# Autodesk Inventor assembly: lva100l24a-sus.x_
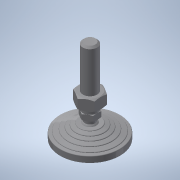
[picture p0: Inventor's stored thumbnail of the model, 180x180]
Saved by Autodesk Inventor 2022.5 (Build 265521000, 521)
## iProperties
Part Number: lva100l24a-sus.x_
Material: 一般
Document SubType Name: Assembly
Designer: ImaoCorp
Sending System: SOLIDWORKS 2017-2017317
MC: AMD64
MC_MODEL: Intel64 Family 6 Model 60 Stepping 3, GenuineIntel
OS: Windows_NT
FRU: Parasolid Version 29.0, build 201,  4-17-2017
FORMAT: text
GUISE: transmit
KEY: lva100l24a-sus
FILE: lva100l24a-sus.x_t
DATE: Mon Jul 01 18:04:37 2019
Author: ImaoCorp
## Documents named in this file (3)
- X:\14_SW2022-Inv2022\00_全2023-1023新製品(TCC)まで\l\lva100l24a-sus\LVA100L24A-SUS.iam
- X:\14_SW2022-Inv2022\00_全2023-1023新製品(TCC)まで\l\lva100l24a-sus\lva100l24a-sus_01.ipt
- X:\14_SW2022-Inv2022\00_全2023-1023新製品(TCC)まで\l\lva100l24a-sus\lva100l24a-sus_02.ipt
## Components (2 placed, 2 different names)
1. lva100l24a-sus_01
2. lva100l24a-sus_02
